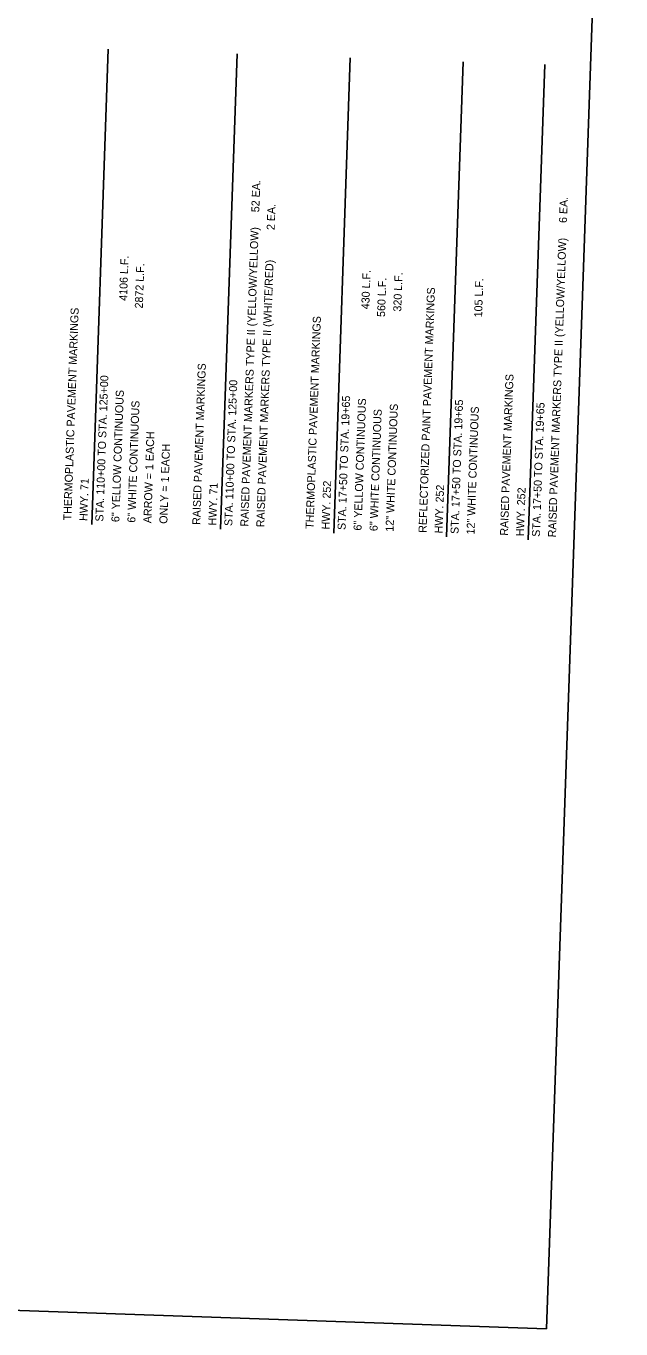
# Model space of a CAD drawing. Extents: x 633912 to 634995, y 289794 to 291427.
# Drawn here: x 634549 to 634995, y 289794 to 290770 of the extents above; entities that cross this region are included whole.
import ezdxf

# ---------------------------------------------------------------- set-up
doc = ezdxf.new("R2010")
doc.units = 0
doc.layers.add('Level 63', color=7, linetype='Continuous')
doc.layers.add('ROAD', color=7, linetype='Continuous')

msp = doc.modelspace()

# ---------------------------------------------------------------- linework, layer by layer
at = {"layer": 'Level 63'}
msp.add_lwpolyline([(634938.65, 289793.65), (633912.26, 289829.49), (633957.19, 291116.06), (634006.28, 291114.34), (634017.21, 291427.35), (634994.51, 291393.22)], close=True, dxfattribs=at)
at = {"layer": 'ROAD'}
for p, q in [((634597.87, 290396.73), (634610.31, 290753.03)), ((634694.52, 290393.35), (634706.96, 290749.66)), ((634779.23, 290390.39), (634791.67, 290746.7)), ((634863.9, 290387.44), (634876.34, 290743.74)), ((634924.95, 290385.3), (634937.39, 290741.61))]:
    msp.add_line(p, q, dxfattribs=at)

# ---------------------------------------------------------------- texts
for s, p in [('RAISED PAVEMENT MARKERS TYPE II (YELLOW/YELLOW)     52 EA.', (634715.2, 290395.09)), ('RAISED PAVEMENT MARKERS TYPE II (YELLOW/YELLOW)     6 EA.', (634945.79, 290387.04)), ('RAISED PAVEMENT MARKERS TYPE II (WHITE/RED)          2 EA.', (634727.19, 290394.67)), ('6" YELLOW CONTINUOUS                              4106 L.F.', (634618.55, 290398.47)), ('6" WHITE CONTINUOUS                               2872 L.F.', (634630.55, 290398.05)), ('6" YELLOW CONTINUOUS                              430 L.F.', (634800.07, 290392.13)), ('12" WHITE CONTINUOUS                               320 L.F.', (634824.06, 290391.29)), ('6" WHITE CONTINUOUS                               560 L.F.', (634812.07, 290391.71)), ('REFLECTORIZED PAINT PAVEMENT MARKINGS', (634848.77, 290390.43)), ('12" WHITE CONTINUOUS                              105 L.F.', (634884.74, 290389.17)), ('THERMOPLASTIC PAVEMENT MARKINGS', (634582.58, 290399.72)), ('THERMOPLASTIC PAVEMENT MARKINGS', (634764.1, 290393.38)), ('RAISED PAVEMENT MARKINGS', (634679.22, 290396.35)), ('STA. 110+00 TO STA. 125+00', (634606.56, 290398.88)), ('STA. 110+00 TO STA. 125+00', (634703.21, 290395.51)), ('RAISED PAVEMENT MARKINGS', (634909.82, 290388.29)), ('STA. 17+50 TO STA. 19+65', (634788.08, 290392.55)), ('STA. 17+50 TO STA. 19+65', (634872.75, 290389.59)), ('STA. 17+50 TO STA. 19+65', (634933.8, 290387.46)), ('ARROW = 1 EACH', (634642.54, 290397.63)), ('ONLY = 1 EACH', (634654.53, 290397.21)), ('HWY. 71', (634594.57, 290399.3)), ('HWY. 71', (634691.22, 290395.93)), ('HWY. 252', (634776.09, 290392.96)), ('HWY. 252', (634860.76, 290390.01)), ('HWY. 252', (634921.81, 290387.88))]:
    msp.add_text(s, height=6, rotation=87.99999, dxfattribs=at).set_placement(p)

doc.saveas('drawing.dxf')
